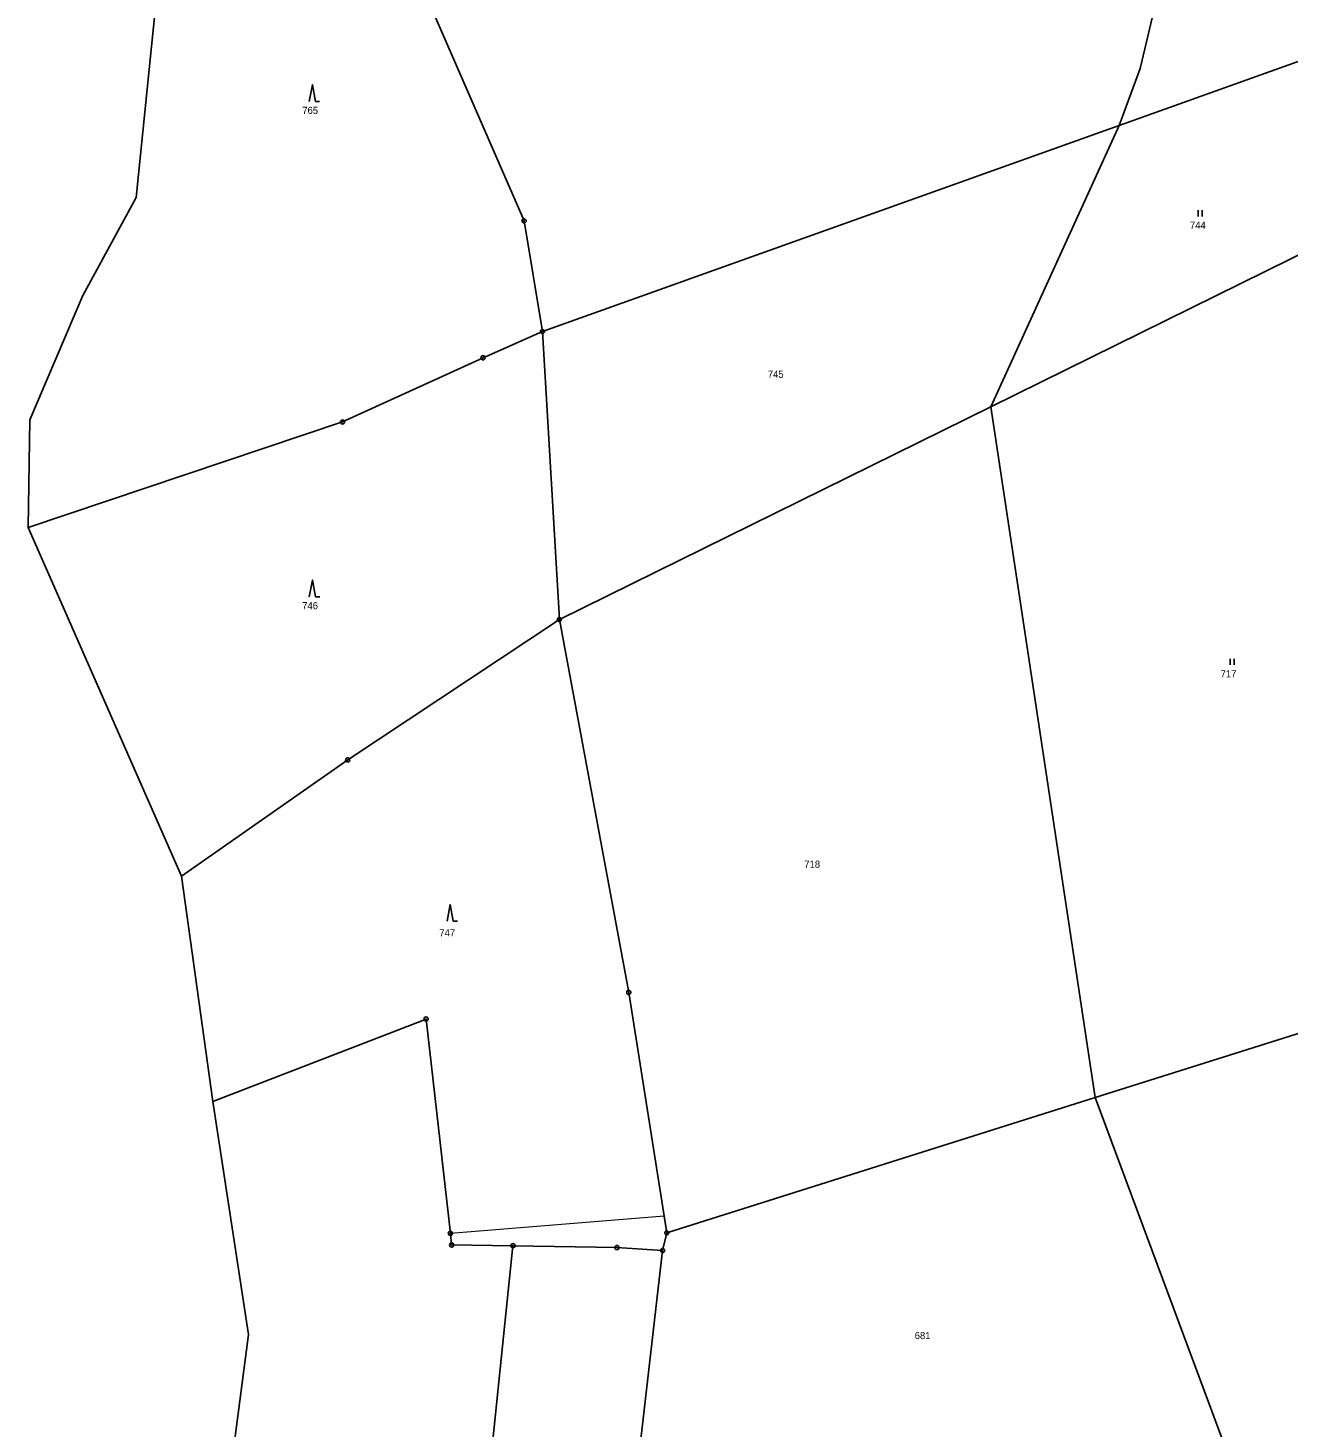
# Model space of a CAD drawing. Extents: x -719614 to -717765, y -1095834 to -1093862.
# Drawn here: x -719381.2 to -719079.2, y -1094701.4 to -1094365.9 of the extents above; entities that cross this region are included whole.
import ezdxf
from ezdxf.enums import TextEntityAlignment as Align

# ---------------------------------------------------------------- set-up
doc = ezdxf.new("R2010")
doc.units = 0
doc.header["$LTSCALE"] = 0.68
for name, color, linetype, lineweight in [('1', 7, 'Continuous', 25), ('13', 7, 'Continuous', 13), ('3', 7, 'Continuous', 25), ('8', 7, 'Continuous', 25)]:
    doc.layers.add(name, color=color, linetype=linetype, lineweight=lineweight)
doc.layers.add('2', color=7, linetype='Continuous')

msp = doc.modelspace()

# ---------------------------------------------------------------- linework, layer by layer
at = {"layer": '1'}
for p, q in [((-719262.4, -1094412.11), (-719311.75, -1094298.79)), ((-719114.85, -1094375.65), (-719098.35, -1094305.6)), ((-719350.6, -1094360.12), (-719355.3, -1094406.51)), ((-719119.88, -1094389.25), (-719062.72, -1094368.82)), ((-719119.88, -1094389.25), (-719114.85, -1094375.65)), ((-719258.01, -1094438.63), (-719119.88, -1094389.25)), ((-719119.88, -1094389.25), (-719150.62, -1094456.67)), ((-719355.3, -1094406.51), (-719368.07, -1094430.01)), ((-719258.01, -1094438.63), (-719262.4, -1094412.11)), ((-719072.77, -1094418.27), (-719150.62, -1094456.67)), ((-719368.07, -1094430.01), (-719380.81, -1094459.79)), ((-719272.24, -1094444.92), (-719258.01, -1094438.63)), ((-719253.96, -1094507.64), (-719258.01, -1094438.63)), ((-719305.89, -1094460.31), (-719272.24, -1094444.92)), ((-719253.96, -1094507.64), (-719150.62, -1094456.67)), ((-719150.62, -1094456.67), (-719125.67, -1094622.21)), ((-719380.81, -1094459.79), (-719381.21, -1094485.56)), ((-719381.21, -1094485.56), (-719305.89, -1094460.31)), ((-719381.21, -1094485.56), (-719344.42, -1094569.17)), ((-719304.64, -1094541.28), (-719253.96, -1094507.64)), ((-719253.96, -1094507.64), (-719237.33, -1094597.01)), ((-719344.42, -1094569.17), (-719304.64, -1094541.28)), ((-719344.42, -1094569.17), (-719336.91, -1094623.17)), ((-719125.67, -1094622.21), (-719042.13, -1094595.83)), ((-719237.33, -1094597.01), (-719228.22, -1094654.6)), ((-719285.86, -1094603.37), (-719336.91, -1094623.17)), ((-719280.05, -1094654.74), (-719285.86, -1094603.37)), ((-719336.91, -1094623.17), (-719328.41, -1094678.93)), ((-719228.22, -1094654.6), (-719125.67, -1094622.21)), ((-719090.93, -1094715.53), (-719125.67, -1094622.21)), ((-719279.76, -1094657.5), (-719280.05, -1094654.74)), ((-719229.23, -1094658.84), (-719228.22, -1094654.6)), ((-719265.07, -1094657.69), (-719279.76, -1094657.5)), ((-719271.63, -1094721.23), (-719265.07, -1094657.69)), ((-719265.07, -1094657.69), (-719240.15, -1094658.13)), ((-719240.15, -1094658.13), (-719229.23, -1094658.84)), ((-719229.23, -1094658.84), (-719237.65, -1094731.36)), ((-719328.41, -1094678.93), (-719335.91, -1094736.24))]:
    msp.add_line(p, q, dxfattribs=at)
at = {"layer": '13'}
msp.add_lwpolyline([(-719280.05, -1094654.74), (-719279.76, -1094657.5), (-719265.07, -1094657.69), (-719240.15, -1094658.13), (-719229.23, -1094658.84), (-719228.22, -1094654.6), (-719228.85, -1094650.62)], close=True, dxfattribs=at)
at = {"layer": '3'}
for p, q in [((-719312.36, -1094383.51), (-719311.364, -1094383.51)), ((-719100.991, -1094411.04), (-719100.991, -1094409.54)), ((-719099.99, -1094411.04), (-719099.99, -1094409.54)), ((-719312.35, -1094502.2), (-719311.354, -1094502.2)), ((-719093.321, -1094518.54), (-719093.321, -1094517.04)), ((-719092.32, -1094518.54), (-719092.32, -1094517.04)), ((-719279.36, -1094579.96), (-719278.364, -1094579.96))]:
    msp.add_line(p, q, dxfattribs=at)
for points in [[(-719312.36, -1094383.51), (-719313.11, -1094379.51), (-719313.86, -1094383.51)], [(-719312.35, -1094502.2), (-719313.1, -1094498.2), (-719313.85, -1094502.2)], [(-719279.36, -1094579.96), (-719280.11, -1094575.96), (-719280.86, -1094579.96)]]:
    msp.add_lwpolyline(points, dxfattribs=at)
at = {"layer": '8'}
for centre, radius in [((-719262.4, -1094412.1099), 0.5), ((-719262.4, -1094412.1099), 0.0303), ((-719258.01, -1094438.6299), 0.5), ((-719258.01, -1094438.6299), 0.0303), ((-719272.24, -1094444.9199), 0.5), ((-719272.24, -1094444.9199), 0.0303), ((-719305.89, -1094460.3099), 0.5), ((-719305.89, -1094460.3099), 0.0303), ((-719253.96, -1094507.6399), 0.5), ((-719253.96, -1094507.6399), 0.0303), ((-719304.64, -1094541.2799), 0.5), ((-719304.64, -1094541.2799), 0.0303), ((-719237.33, -1094597.0099), 0.5), ((-719237.33, -1094597.0099), 0.0303), ((-719285.86, -1094603.3699), 0.5), ((-719285.86, -1094603.3699), 0.0303), ((-719280.05, -1094654.7399), 0.5), ((-719279.76, -1094657.4999), 0.5), ((-719280.05, -1094654.7399), 0.0303), ((-719228.22, -1094654.5999), 0.5), ((-719228.22, -1094654.5999), 0.0303), ((-719279.76, -1094657.4999), 0.0303), ((-719265.07, -1094657.6899), 0.5), ((-719265.07, -1094657.6899), 0.0303), ((-719240.15, -1094658.1299), 0.5), ((-719240.15, -1094658.1299), 0.0303), ((-719229.23, -1094658.8399), 0.5), ((-719229.23, -1094658.8399), 0.0303)]:
    msp.add_circle(centre, radius, dxfattribs=at)

# ---------------------------------------------------------------- texts
at = {"layer": '2'}
for s, p in [('765', (-719313.629, -1094386.492)), ('744', (-719101.039, -1094414.022)), ('745', (-719202.149, -1094449.722)), ('746', (-719313.659, -1094505.182)), ('717', (-719093.709, -1094521.522)), ('718', (-719193.399, -1094567.122)), ('747', (-719280.809, -1094583.562)), ('681', (-719166.959, -1094680.072))]:
    msp.add_text(s, height=1.7, dxfattribs=at).set_placement(p, align=Align.CENTER)

doc.saveas('drawing.dxf')
